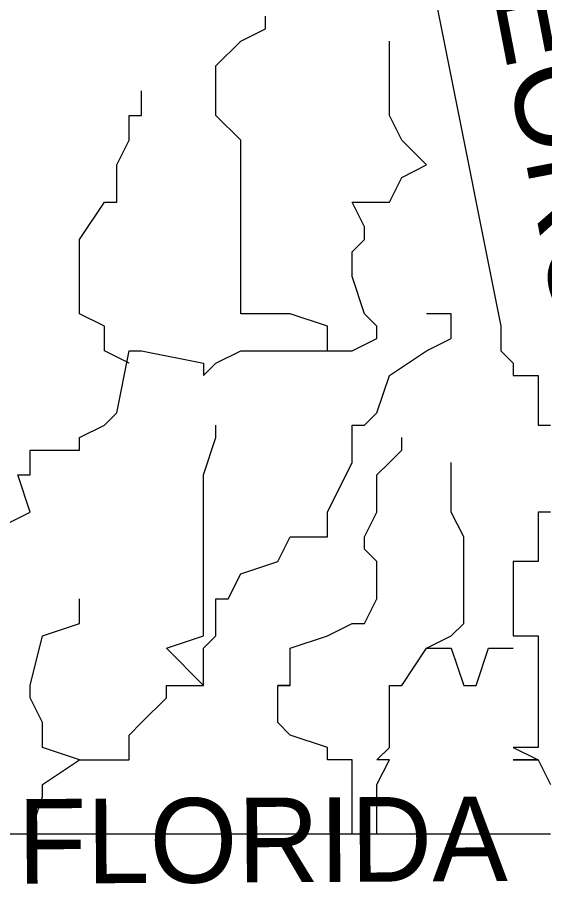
# Model space of a CAD drawing. Extents: x -12822 to 16384, y -6351 to 1913.
# Drawn here: x 75.26 to 86.43, y 821.12 to 839.81 of the extents above; entities that cross this region are included whole.
import ezdxf

# ---------------------------------------------------------------- set-up
doc = ezdxf.new("R2010")
doc.units = 0
doc.layers.add('great seal', color=7, linetype='Continuous')

msp = doc.modelspace()

# ---------------------------------------------------------------- linework, layer by layer
at = {"layer": 'great seal'}
msp.add_line((77.627, 832.483), (77.627, 832.483), dxfattribs=at)
msp.add_line((77.627, 832.483), (77.627, 832.483), dxfattribs=at)
msp.add_line((77.627, 832.483), (77.627, 832.483), dxfattribs=at)
msp.add_line((77.627, 832.483), (77.627, 832.483), dxfattribs=at)
msp.add_line((77.627, 832.483), (77.627, 832.483), dxfattribs=at)
msp.add_line((77.627, 832.483), (77.627, 832.483), dxfattribs=at)
for points in [[(68.693, 819.082), (68.693, 828.278), (71.058, 844.57), (71.058, 845.095), (71.058, 845.095), (71.058, 845.095), (70.27, 845.095), (70.27, 845.358), (71.058, 845.358), (83.145, 845.095), (85.51, 833.271), (85.51, 832.745), (85.773, 832.483), (85.773, 832.22), (85.773, 832.22), (86.299, 832.22), (86.299, 831.432), (86.299, 831.169), (86.561, 831.169)], [(68.693, 819.082), (68.693, 828.278), (71.058, 844.57), (71.058, 845.095), (71.058, 845.095), (71.058, 845.095), (70.27, 845.095), (70.27, 845.358), (71.058, 845.358), (83.145, 845.095), (85.51, 833.271), (85.51, 832.745), (85.773, 832.483), (85.773, 832.22), (85.773, 832.22), (86.299, 832.22), (86.299, 831.432), (86.299, 831.169), (86.561, 831.169)], [(68.693, 819.082), (68.693, 828.278), (71.058, 844.57), (71.058, 845.095), (71.058, 845.095), (71.058, 845.095), (70.27, 845.095), (70.27, 845.358), (71.058, 845.358), (83.145, 845.095), (85.51, 833.271), (85.51, 832.745), (85.773, 832.483), (85.773, 832.22), (85.773, 832.22), (86.299, 832.22), (86.299, 831.432), (86.299, 831.169), (86.561, 831.169)], [(81.832, 832.745), (81.832, 833.271), (81.043, 833.534), (80.78, 833.534), (79.992, 833.534), (79.992, 834.848), (79.992, 834.848), (79.992, 835.11), (79.992, 835.899), (79.992, 836.424), (79.992, 837.212), (79.467, 837.738), (79.467, 838.789), (79.992, 839.315), (80.518, 839.577), (80.518, 839.84)], [(81.832, 832.745), (81.832, 833.271), (81.043, 833.534), (80.78, 833.534), (79.992, 833.534), (79.992, 834.848), (79.992, 834.848), (79.992, 835.11), (79.992, 835.899), (79.992, 836.424), (79.992, 837.212), (79.467, 837.738), (79.467, 838.789), (79.992, 839.315), (80.518, 839.577), (80.518, 839.84)], [(81.832, 832.745), (81.832, 833.271), (81.043, 833.534), (80.78, 833.534), (79.992, 833.534), (79.992, 834.848), (79.992, 834.848), (79.992, 835.11), (79.992, 835.899), (79.992, 836.424), (79.992, 837.212), (79.467, 837.738), (79.467, 838.789), (79.992, 839.315), (80.518, 839.577), (80.518, 839.84)], [(75, 829.067), (75.525, 829.329), (75.262, 830.118), (75.525, 830.118), (75.525, 830.643), (76.576, 830.643), (76.576, 830.906), (76.576, 830.906), (77.102, 831.169), (77.365, 831.432), (77.627, 832.745), (77.89, 832.745), (79.204, 832.483), (79.204, 832.22), (79.467, 832.483), (79.992, 832.745), (80.78, 832.745), (81.832, 832.745), (82.357, 832.745), (82.883, 833.008), (82.883, 833.271), (82.62, 833.534), (82.62, 833.534), (82.357, 834.322), (82.357, 834.848), (82.62, 835.11), (82.62, 835.373), (82.357, 835.899), (83.145, 835.899), (83.408, 836.424), (83.934, 836.687), (83.408, 837.212), (83.408, 837.212), (83.145, 837.738), (83.145, 838.263), (83.145, 839.315)], [(75, 829.067), (75.525, 829.329), (75.262, 830.118), (75.525, 830.118), (75.525, 830.643), (76.576, 830.643), (76.576, 830.906), (76.576, 830.906), (77.102, 831.169), (77.365, 831.432), (77.627, 832.745), (77.89, 832.745), (79.204, 832.483), (79.204, 832.22), (79.467, 832.483), (79.992, 832.745), (80.78, 832.745), (81.832, 832.745), (82.357, 832.745), (82.883, 833.008), (82.883, 833.271), (82.62, 833.534), (82.62, 833.534), (82.357, 834.322), (82.357, 834.848), (82.62, 835.11), (82.62, 835.373), (82.357, 835.899), (83.145, 835.899), (83.408, 836.424), (83.934, 836.687), (83.408, 837.212), (83.408, 837.212), (83.145, 837.738), (83.145, 838.263), (83.145, 839.315)], [(75, 829.067), (75.525, 829.329), (75.262, 830.118), (75.525, 830.118), (75.525, 830.643), (76.576, 830.643), (76.576, 830.906), (76.576, 830.906), (77.102, 831.169), (77.365, 831.432), (77.627, 832.745), (77.89, 832.745), (79.204, 832.483), (79.204, 832.22), (79.467, 832.483), (79.992, 832.745), (80.78, 832.745), (81.832, 832.745), (82.357, 832.745), (82.883, 833.008), (82.883, 833.271), (82.62, 833.534), (82.62, 833.534), (82.357, 834.322), (82.357, 834.848), (82.62, 835.11), (82.62, 835.373), (82.357, 835.899), (83.145, 835.899), (83.408, 836.424), (83.934, 836.687), (83.408, 837.212), (83.408, 837.212), (83.145, 837.738), (83.145, 838.263), (83.145, 839.315)], [(77.627, 832.483), (77.102, 832.745), (77.102, 833.008), (77.102, 833.271), (76.576, 833.534), (76.576, 834.322), (76.576, 834.848), (76.576, 835.11), (76.576, 835.11), (77.102, 835.899), (77.365, 835.899), (77.365, 836.687), (77.627, 837.212), (77.627, 837.212), (77.627, 837.738), (77.89, 837.738), (77.89, 838.263)], [(77.627, 832.483), (77.102, 832.745), (77.102, 833.008), (77.102, 833.271), (76.576, 833.534), (76.576, 834.322), (76.576, 834.848), (76.576, 835.11), (76.576, 835.11), (77.102, 835.899), (77.365, 835.899), (77.365, 836.687), (77.627, 837.212), (77.627, 837.212), (77.627, 837.738), (77.89, 837.738), (77.89, 838.263)], [(77.627, 832.483), (77.102, 832.745), (77.102, 833.008), (77.102, 833.271), (76.576, 833.534), (76.576, 834.322), (76.576, 834.848), (76.576, 835.11), (76.576, 835.11), (77.102, 835.899), (77.365, 835.899), (77.365, 836.687), (77.627, 837.212), (77.627, 837.212), (77.627, 837.738), (77.89, 837.738), (77.89, 838.263)], [(79.204, 825.651), (79.204, 825.651), (79.204, 826.439), (79.467, 826.702), (79.467, 826.965), (79.467, 827.49), (79.729, 827.49), (79.992, 828.016), (80.78, 828.278), (81.043, 828.804), (81.832, 828.804), (81.832, 829.329), (82.357, 830.381), (82.357, 830.906), (82.357, 830.906), (82.357, 831.169), (82.62, 831.169), (82.883, 831.432), (83.145, 832.22), (83.934, 832.745), (84.459, 833.008), (84.459, 833.271), (84.459, 833.534), (83.934, 833.534)], [(79.204, 825.651), (79.204, 825.651), (79.204, 826.439), (79.467, 826.702), (79.467, 826.965), (79.467, 827.49), (79.729, 827.49), (79.992, 828.016), (80.78, 828.278), (81.043, 828.804), (81.832, 828.804), (81.832, 829.329), (82.357, 830.381), (82.357, 830.906), (82.357, 830.906), (82.357, 831.169), (82.62, 831.169), (82.883, 831.432), (83.145, 832.22), (83.934, 832.745), (84.459, 833.008), (84.459, 833.271), (84.459, 833.534), (83.934, 833.534)], [(79.204, 825.651), (79.204, 825.651), (79.204, 826.439), (79.467, 826.702), (79.467, 826.965), (79.467, 827.49), (79.729, 827.49), (79.992, 828.016), (80.78, 828.278), (81.043, 828.804), (81.832, 828.804), (81.832, 829.329), (82.357, 830.381), (82.357, 830.906), (82.357, 830.906), (82.357, 831.169), (82.62, 831.169), (82.883, 831.432), (83.145, 832.22), (83.934, 832.745), (84.459, 833.008), (84.459, 833.271), (84.459, 833.534), (83.934, 833.534)], [(76.576, 824.074), (76.576, 824.074), (77.102, 824.074), (77.365, 824.074), (77.627, 824.074), (77.627, 824.337), (77.627, 824.6), (77.89, 824.863), (78.416, 825.388), (78.416, 825.651), (79.204, 825.651), (79.204, 825.651), (78.416, 826.439), (79.204, 826.702), (79.204, 826.965), (79.204, 827.49), (79.204, 828.016), (79.204, 828.278), (79.204, 828.804), (79.204, 828.804), (79.204, 829.329), (79.204, 830.118), (79.467, 830.906), (79.467, 830.906), (79.467, 831.169)], [(76.576, 824.074), (76.576, 824.074), (77.102, 824.074), (77.365, 824.074), (77.627, 824.074), (77.627, 824.337), (77.627, 824.6), (77.89, 824.863), (78.416, 825.388), (78.416, 825.651), (79.204, 825.651), (79.204, 825.651), (78.416, 826.439), (79.204, 826.702), (79.204, 826.965), (79.204, 827.49), (79.204, 828.016), (79.204, 828.278), (79.204, 828.804), (79.204, 828.804), (79.204, 829.329), (79.204, 830.118), (79.467, 830.906), (79.467, 830.906), (79.467, 831.169)], [(76.576, 824.074), (76.576, 824.074), (77.102, 824.074), (77.365, 824.074), (77.627, 824.074), (77.627, 824.337), (77.627, 824.6), (77.89, 824.863), (78.416, 825.388), (78.416, 825.651), (79.204, 825.651), (79.204, 825.651), (78.416, 826.439), (79.204, 826.702), (79.204, 826.965), (79.204, 827.49), (79.204, 828.016), (79.204, 828.278), (79.204, 828.804), (79.204, 828.804), (79.204, 829.329), (79.204, 830.118), (79.467, 830.906), (79.467, 830.906), (79.467, 831.169)], [(82.357, 822.498), (82.357, 823.286), (82.357, 823.549), (82.357, 824.074), (82.357, 824.074), (81.832, 824.074), (81.832, 824.337), (81.043, 824.6), (80.78, 824.863), (80.78, 825.388), (80.78, 825.651), (81.043, 825.651), (80.78, 825.651), (81.043, 825.651), (81.043, 826.439), (81.832, 826.702), (82.357, 826.965), (82.357, 826.965), (82.62, 826.965), (82.883, 827.49), (82.883, 827.49), (82.883, 828.016), (82.883, 828.278), (82.883, 828.278), (82.62, 828.541), (82.62, 828.804), (82.883, 829.329), (82.883, 830.118), (83.145, 830.381), (83.408, 830.643), (83.408, 830.906)], [(82.357, 822.498), (82.357, 823.286), (82.357, 823.549), (82.357, 824.074), (82.357, 824.074), (81.832, 824.074), (81.832, 824.337), (81.043, 824.6), (80.78, 824.863), (80.78, 825.388), (80.78, 825.651), (81.043, 825.651), (80.78, 825.651), (81.043, 825.651), (81.043, 826.439), (81.832, 826.702), (82.357, 826.965), (82.357, 826.965), (82.62, 826.965), (82.883, 827.49), (82.883, 827.49), (82.883, 828.016), (82.883, 828.278), (82.883, 828.278), (82.62, 828.541), (82.62, 828.804), (82.883, 829.329), (82.883, 830.118), (83.145, 830.381), (83.408, 830.643), (83.408, 830.906)], [(82.357, 822.498), (82.357, 823.286), (82.357, 823.549), (82.357, 824.074), (82.357, 824.074), (81.832, 824.074), (81.832, 824.337), (81.043, 824.6), (80.78, 824.863), (80.78, 825.388), (80.78, 825.651), (81.043, 825.651), (80.78, 825.651), (81.043, 825.651), (81.043, 826.439), (81.832, 826.702), (82.357, 826.965), (82.357, 826.965), (82.62, 826.965), (82.883, 827.49), (82.883, 827.49), (82.883, 828.016), (82.883, 828.278), (82.883, 828.278), (82.62, 828.541), (82.62, 828.804), (82.883, 829.329), (82.883, 830.118), (83.145, 830.381), (83.408, 830.643), (83.408, 830.906)], [(83.934, 826.439), (83.934, 826.439), (84.459, 826.702), (84.722, 826.965), (84.722, 826.965), (84.722, 827.49), (84.722, 828.016), (84.722, 828.278), (84.722, 828.541), (84.722, 828.804), (84.459, 829.329), (84.459, 829.329), (84.459, 830.381)], [(83.934, 826.439), (83.934, 826.439), (84.459, 826.702), (84.722, 826.965), (84.722, 826.965), (84.722, 827.49), (84.722, 828.016), (84.722, 828.278), (84.722, 828.541), (84.722, 828.804), (84.459, 829.329), (84.459, 829.329), (84.459, 830.381)], [(83.934, 826.439), (83.934, 826.439), (84.459, 826.702), (84.722, 826.965), (84.722, 826.965), (84.722, 827.49), (84.722, 828.016), (84.722, 828.278), (84.722, 828.541), (84.722, 828.804), (84.459, 829.329), (84.459, 829.329), (84.459, 830.381)], [(86.561, 829.329), (86.299, 829.329), (86.299, 829.329), (86.299, 829.329), (86.299, 829.067), (86.299, 828.804), (86.299, 828.804), (86.299, 828.804), (86.299, 828.804), (86.299, 828.804), (86.299, 828.541), (86.299, 828.541), (86.299, 828.541), (86.299, 828.278), (86.299, 828.278), (85.773, 828.278), (85.773, 828.278), (85.773, 828.278), (85.773, 828.016), (85.773, 828.016), (85.773, 827.49), (85.773, 827.49), (85.773, 827.49), (85.773, 827.49), (85.773, 827.49), (85.773, 827.49), (85.773, 827.49), (85.773, 826.965), (85.773, 826.965), (85.773, 826.965), (85.773, 826.965), (85.773, 826.965), (85.773, 826.965), (85.773, 826.702), (86.299, 826.702), (86.299, 826.439), (86.299, 826.439), (86.299, 826.439), (86.299, 825.651), (86.299, 825.651), (86.299, 825.651), (86.299, 825.651), (86.299, 825.651), (86.299, 825.651), (86.299, 825.388), (86.299, 824.863), (86.299, 824.863), (86.299, 824.863), (86.299, 824.6), (86.299, 824.6), (86.299, 824.337), (86.299, 824.337), (85.773, 824.337), (85.773, 824.337), (85.773, 824.337), (85.773, 824.337), (86.299, 824.074), (86.299, 824.074), (85.773, 824.074), (86.299, 824.074), (86.299, 824.074), (86.299, 824.074), (86.561, 823.549)], [(86.561, 829.329), (86.299, 829.329), (86.299, 829.329), (86.299, 829.329), (86.299, 829.067), (86.299, 828.804), (86.299, 828.804), (86.299, 828.804), (86.299, 828.804), (86.299, 828.804), (86.299, 828.541), (86.299, 828.541), (86.299, 828.541), (86.299, 828.278), (86.299, 828.278), (85.773, 828.278), (85.773, 828.278), (85.773, 828.278), (85.773, 828.016), (85.773, 828.016), (85.773, 827.49), (85.773, 827.49), (85.773, 827.49), (85.773, 827.49), (85.773, 827.49), (85.773, 827.49), (85.773, 827.49), (85.773, 826.965), (85.773, 826.965), (85.773, 826.965), (85.773, 826.965), (85.773, 826.965), (85.773, 826.965), (85.773, 826.702), (86.299, 826.702), (86.299, 826.439), (86.299, 826.439), (86.299, 826.439), (86.299, 825.651), (86.299, 825.651), (86.299, 825.651), (86.299, 825.651), (86.299, 825.651), (86.299, 825.651), (86.299, 825.388), (86.299, 824.863), (86.299, 824.863), (86.299, 824.863), (86.299, 824.6), (86.299, 824.6), (86.299, 824.337), (86.299, 824.337), (85.773, 824.337), (85.773, 824.337), (85.773, 824.337), (85.773, 824.337), (86.299, 824.074), (86.299, 824.074), (85.773, 824.074), (86.299, 824.074), (86.299, 824.074), (86.299, 824.074), (86.561, 823.549)], [(86.561, 829.329), (86.299, 829.329), (86.299, 829.329), (86.299, 829.329), (86.299, 829.067), (86.299, 828.804), (86.299, 828.804), (86.299, 828.804), (86.299, 828.804), (86.299, 828.804), (86.299, 828.541), (86.299, 828.541), (86.299, 828.541), (86.299, 828.278), (86.299, 828.278), (85.773, 828.278), (85.773, 828.278), (85.773, 828.278), (85.773, 828.016), (85.773, 828.016), (85.773, 827.49), (85.773, 827.49), (85.773, 827.49), (85.773, 827.49), (85.773, 827.49), (85.773, 827.49), (85.773, 827.49), (85.773, 826.965), (85.773, 826.965), (85.773, 826.965), (85.773, 826.965), (85.773, 826.965), (85.773, 826.965), (85.773, 826.702), (86.299, 826.702), (86.299, 826.439), (86.299, 826.439), (86.299, 826.439), (86.299, 825.651), (86.299, 825.651), (86.299, 825.651), (86.299, 825.651), (86.299, 825.651), (86.299, 825.651), (86.299, 825.388), (86.299, 824.863), (86.299, 824.863), (86.299, 824.863), (86.299, 824.6), (86.299, 824.6), (86.299, 824.337), (86.299, 824.337), (85.773, 824.337), (85.773, 824.337), (85.773, 824.337), (85.773, 824.337), (86.299, 824.074), (86.299, 824.074), (85.773, 824.074), (86.299, 824.074), (86.299, 824.074), (86.299, 824.074), (86.561, 823.549)], [(75.525, 822.498), (75.788, 823.286), (75.788, 823.549), (76.576, 824.074), (76.576, 824.074), (76.576, 824.074), (75.788, 824.337), (75.788, 824.6), (75.788, 824.863), (75.525, 825.388), (75.525, 825.651), (75.525, 825.651), (75.788, 826.702), (76.576, 826.965), (76.576, 827.49)], [(75.525, 822.498), (75.788, 823.286), (75.788, 823.549), (76.576, 824.074), (76.576, 824.074), (76.576, 824.074), (75.788, 824.337), (75.788, 824.6), (75.788, 824.863), (75.525, 825.388), (75.525, 825.651), (75.525, 825.651), (75.788, 826.702), (76.576, 826.965), (76.576, 827.49)], [(75.525, 822.498), (75.788, 823.286), (75.788, 823.549), (76.576, 824.074), (76.576, 824.074), (76.576, 824.074), (75.788, 824.337), (75.788, 824.6), (75.788, 824.863), (75.525, 825.388), (75.525, 825.651), (75.525, 825.651), (75.788, 826.702), (76.576, 826.965), (76.576, 827.49)], [(82.883, 822.498), (82.883, 823.286), (82.883, 823.286), (82.883, 823.549), (83.145, 824.074), (82.883, 824.074), (83.145, 824.337), (83.145, 824.6), (83.145, 824.863), (83.145, 824.863), (83.145, 825.388), (83.145, 825.651), (83.408, 825.651), (83.934, 826.439), (84.459, 826.439), (84.722, 825.651), (84.985, 825.651), (85.247, 826.439), (85.51, 826.439), (85.773, 826.439)], [(82.883, 822.498), (82.883, 823.286), (82.883, 823.286), (82.883, 823.549), (83.145, 824.074), (82.883, 824.074), (83.145, 824.337), (83.145, 824.6), (83.145, 824.863), (83.145, 824.863), (83.145, 825.388), (83.145, 825.651), (83.408, 825.651), (83.934, 826.439), (84.459, 826.439), (84.722, 825.651), (84.985, 825.651), (85.247, 826.439), (85.51, 826.439), (85.773, 826.439)], [(82.883, 822.498), (82.883, 823.286), (82.883, 823.286), (82.883, 823.549), (83.145, 824.074), (82.883, 824.074), (83.145, 824.337), (83.145, 824.6), (83.145, 824.863), (83.145, 824.863), (83.145, 825.388), (83.145, 825.651), (83.408, 825.651), (83.934, 826.439), (84.459, 826.439), (84.722, 825.651), (84.985, 825.651), (85.247, 826.439), (85.51, 826.439), (85.773, 826.439)], [(86.561, 822.498), (73.16, 822.498), (73.16, 822.235), (73.16, 822.235)], [(86.561, 822.498), (73.16, 822.498), (73.16, 822.235), (73.16, 822.235)], [(86.561, 822.498), (73.16, 822.498), (73.16, 822.235), (73.16, 822.235)]]:
    msp.add_lwpolyline(points, dxfattribs=at)
for radius in [22.994, 22.994, 22.994, 22.389, 22.389, 22.389, 17.779, 17.779, 17.779, 17.222, 17.222, 17.222]:
    msp.add_circle((77.645, 832.298), radius, dxfattribs=at)

# ---------------------------------------------------------------- texts
for s, height, rotation, p in [('GEORGIA', 1.8446, 280.9296, (84.985, 842.205)), ('GEORGIA', 1.8446, 280.9296, (84.985, 842.205)), ('GEORGIA', 1.8446, 280.9296, (84.985, 842.205)), ('FLORIDA', 1.7941, 0.3238, (75.262, 821.447)), ('FLORIDA', 1.7941, 0.3238, (75.262, 821.447)), ('FLORIDA', 1.7941, 0.3238, (75.262, 821.447))]:
    msp.add_text(s, height=height, rotation=rotation, dxfattribs=at).set_placement(p)

doc.saveas('drawing.dxf')
